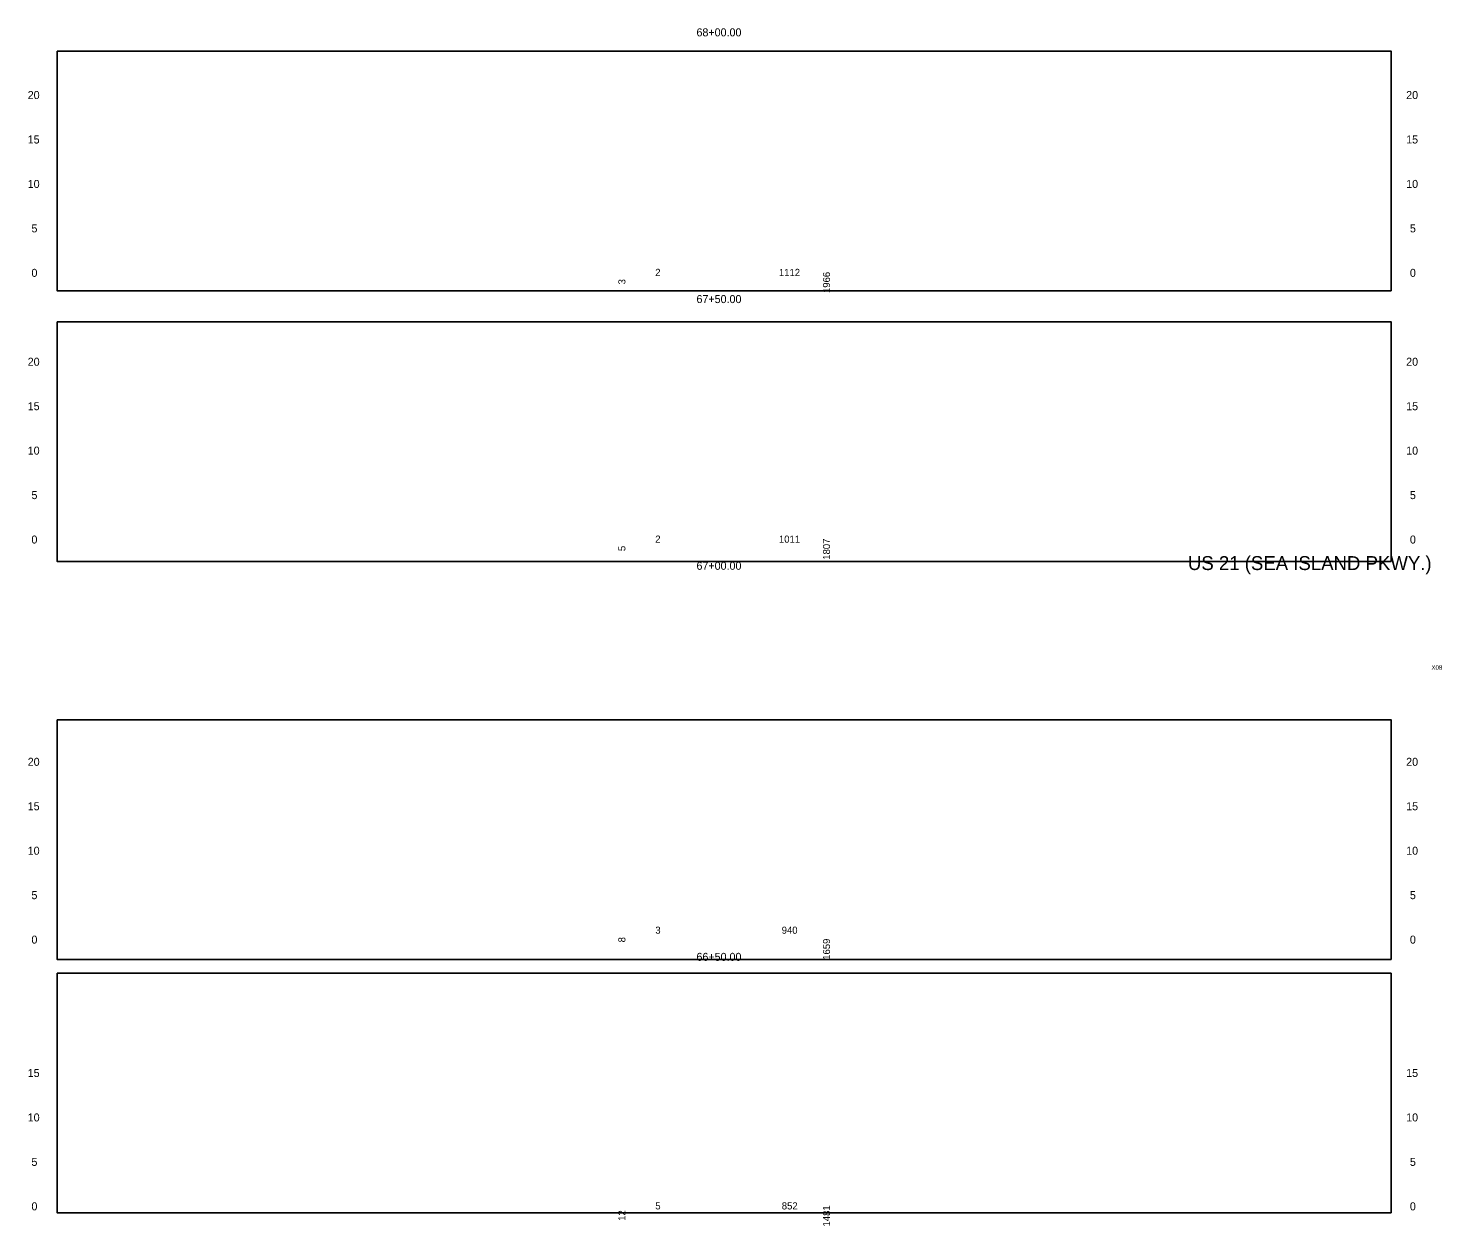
# Model space of a CAD drawing. Extents: x 971 to 1131, y 2203 to 6043.
# Drawn here: x 971.5 to 1130.4, y 3010.1 to 3144.8 of the extents above; entities that cross this region are included whole.
import ezdxf

# ---------------------------------------------------------------- set-up
doc = ezdxf.new("R2010")
doc.units = 0
for name, color, linetype in [('RD_SHT_Misc1', 7, 'Continuous'), ('RD_SHT_ShtClip', 7, 'Continuous'), ('RD_SHT_TX', 7, 'Continuous'), ('RD_XS_TX_Station', 7, 'Continuous')]:
    doc.layers.add(name, color=color, linetype=linetype)

msp = doc.modelspace()

# ---------------------------------------------------------------- linework, layer by layer
at = {"layer": 'RD_SHT_ShtClip'}
for points in [[(974.73, 3142.26), (1124.73, 3142.26), (1124.73, 3115.31), (974.73, 3115.31)], [(974.73, 3111.82), (1124.73, 3111.82), (1124.73, 3084.87), (974.73, 3084.87)], [(974.73, 3067.05), (1124.73, 3067.05), (1124.73, 3040.1), (974.73, 3040.1)], [(974.73, 3038.54), (1124.73, 3038.54), (1124.73, 3011.6), (974.73, 3011.6)]]:
    msp.add_lwpolyline(points, close=True, dxfattribs=at)

# ---------------------------------------------------------------- texts
at = {"layer": 'RD_SHT_Misc1'}
for s, p in [('2', (1041.98, 3116.97)), ('1112', (1055.89, 3116.97)), ('2', (1041.98, 3086.97)), ('1011', (1055.89, 3086.97)), ('3', (1041.99, 3042.98)), ('940', (1056.2, 3042.98)), ('5', (1041.99, 3011.97)), ('852', (1056.21, 3011.97))]:
    msp.add_text(s, height=0.8, dxfattribs=at).set_placement(p)
for s, p in [('1966', (1061.64, 3115.05)), ('3', (1038.63, 3116.02)), ('5', (1038.63, 3086.02)), ('1807', (1061.64, 3085.05)), ('8', (1038.63, 3042.01)), ('1659', (1061.64, 3040.05)), ('1481', (1061.64, 3010.05)), ('12', (1038.63, 3010.69))]:
    msp.add_text(s, height=0.8, rotation=90, dxfattribs=at).set_placement(p)
at = {"layer": 'RD_SHT_TX'}
for s, height, p in [('20', 0.9, (971.42, 3136.87)), ('20', 0.9, (1126.42, 3136.87)), ('15', 0.9, (971.42, 3131.87)), ('15', 0.9, (1126.42, 3131.87)), ('10', 0.9, (971.42, 3126.87)), ('10', 0.9, (1126.42, 3126.87)), ('5', 0.9, (971.84, 3121.87)), ('5', 0.9, (1126.84, 3121.87)), ('0', 0.9, (971.84, 3116.87)), ('0', 0.9, (1126.84, 3116.87)), ('20', 0.9, (971.42, 3106.87)), ('20', 0.9, (1126.42, 3106.87)), ('15', 0.9, (971.42, 3101.87)), ('15', 0.9, (1126.42, 3101.87)), ('10', 0.9, (971.42, 3096.87)), ('10', 0.9, (1126.42, 3096.87)), ('5', 0.9, (971.84, 3091.87)), ('5', 0.9, (1126.84, 3091.87)), ('0', 0.9, (971.84, 3086.87)), ('0', 0.9, (1126.84, 3086.87)), ('US 21 (SEA ISLAND PKWY.)', 1.5625, (1101.88, 3083.89)), ('20', 0.9, (971.42, 3061.87)), ('20', 0.9, (1126.42, 3061.87)), ('15', 0.9, (971.42, 3056.87)), ('15', 0.9, (1126.42, 3056.87)), ('10', 0.9, (971.42, 3051.87)), ('10', 0.9, (1126.42, 3051.87)), ('5', 0.9, (971.84, 3046.87)), ('5', 0.9, (1126.84, 3046.87)), ('0', 0.9, (971.84, 3041.87)), ('0', 0.9, (1126.84, 3041.87)), ('15', 0.9, (971.42, 3026.87)), ('15', 0.9, (1126.42, 3026.87)), ('10', 0.9, (971.42, 3021.87)), ('10', 0.9, (1126.42, 3021.87)), ('5', 0.9, (971.84, 3016.87)), ('5', 0.9, (1126.84, 3016.87)), ('0', 0.9, (971.84, 3011.87)), ('0', 0.9, (1126.84, 3011.87))]:
    msp.add_text(s, height=height, dxfattribs=at).set_placement(p)
msp.add_text('X08', height=0.5, rotation=360, dxfattribs=at).set_placement((1129.26, 3072.68))
at = {"layer": 'RD_XS_TX_Station'}
for s, p in [('68+00.00', (1046.62, 3143.92)), ('67+50.00', (1046.62, 3113.92)), ('67+00.00', (1046.62, 3083.92)), ('66+50.00', (1046.62, 3039.93))]:
    msp.add_text(s, height=0.9, dxfattribs=at).set_placement(p)

doc.saveas('drawing.dxf')
